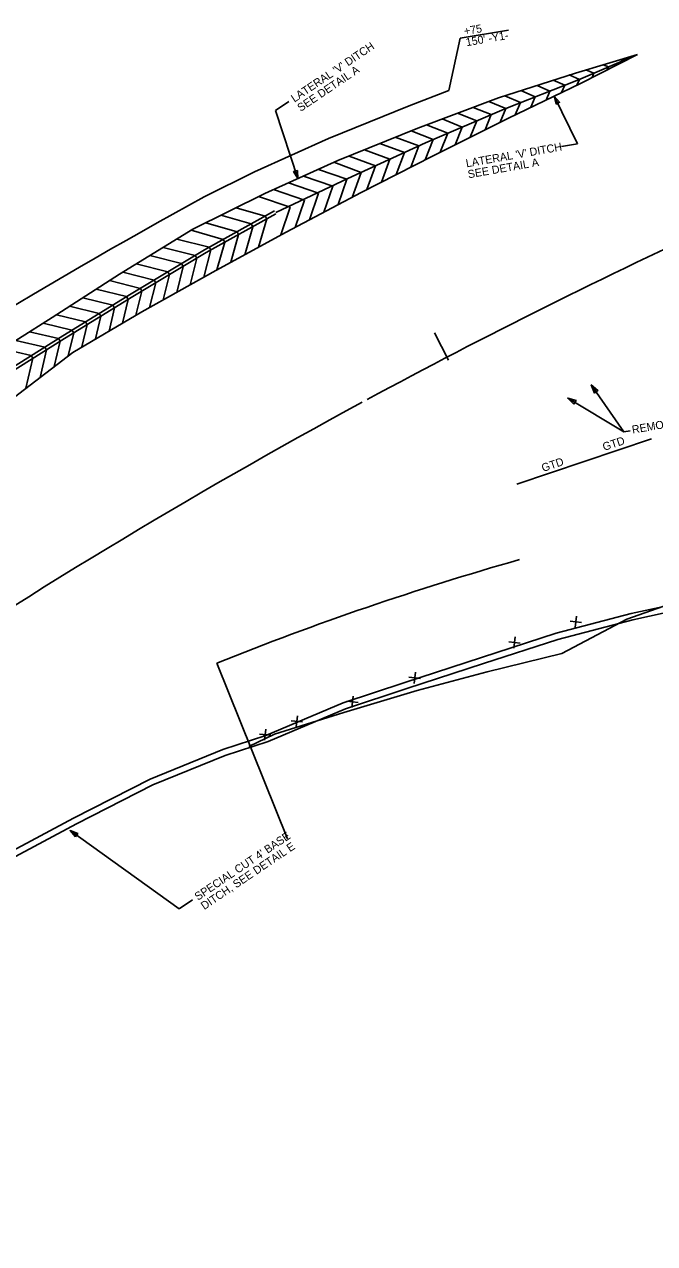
# Model space of a CAD drawing. Extents: x 2384780 to 2405432, y 547869 to 573706.
# Drawn here: x 2392798 to 2393192, y 553270 to 554032 of the extents above; entities that cross this region are included whole.
import ezdxf

# ---------------------------------------------------------------- set-up
doc = ezdxf.new("R2010")
doc.units = 0
for name, color, linetype in [('Old_Level_1', 7, 'Continuous'), ('Old_Level_18', 7, 'Continuous'), ('Old_Level_19', 7, 'Continuous'), ('Old_Level_23', 7, 'Continuous'), ('Old_Level_5', 7, 'Continuous'), ('Old_Level_63', 7, 'Continuous'), ('Prop Ditch Text', 7, 'Continuous'), ('Prop Grade To Drain Pattern Arrows', 7, 'Continuous'), ('Prop Rip Rap Class B Text', 7, 'Continuous'), ('Prop Special Cut Base Ditch Detail CELL', 7, 'Continuous')]:
    doc.layers.add(name, color=color, linetype=linetype)

# ---------------------------------------------------------------- blocks, each defined once
blk = doc.blocks.new('SPOT')
at = {"layer": 'Old_Level_1'}
for p, q in [((-5.48625, 4.61225), (5.48625, -4.61175)), ((-4.608, -5.326), (4.609, 5.325))]:
    blk.add_line(p, q, dxfattribs=at)
blk = doc.blocks.new('AH1')
at = {"layer": 'Old_Level_23'}
blk.add_lwpolyline([(-5.28, 1.32), (0, 0), (-5.28, -1.32)], close=True, dxfattribs=at)

msp = doc.modelspace()

# ---------------------------------------------------------------- linework, layer by layer
at = {"layer": 'Old_Level_1'}
for points in [[(2393152.24, 553806.97), (2393172.69, 553777.71)], [(2393137.51, 553798.8), (2393172.69, 553777.71), (2393176.55, 553778.37)]]:
    msp.add_lwpolyline(points, dxfattribs=at)
at = {"layer": 'Old_Level_18'}
for p, q in [((2393145.46, 553995.35), (2393181.12, 554013.48)), ((2393162.96, 554005.68), (2393159.66, 554006.99)), ((2393172.04, 554009.58), (2393170.39, 554010.24)), ((2393172.04, 554009.58), (2393171.68, 554008.68)), ((2393144.8, 553997.85), (2393138.39, 554000.64)), ((2393153.88, 554001.77), (2393148.93, 554003.74)), ((2393153.88, 554001.77), (2393152.8, 553999.09)), ((2393162.96, 554005.68), (2393162.24, 554003.89)), ((2393126.41, 553990.59), (2393118.4, 553994.07)), ((2393135.61, 553994.22), (2393128.49, 553997.31)), ((2393135.61, 553994.22), (2393133.61, 553989.63)), ((2393144.8, 553997.85), (2393143.25, 553994.28)), ((2393098.82, 553979.74), (2393088.1, 553984.03)), ((2393108.03, 553983.33), (2393098.2, 553987.6)), ((2393117.22, 553986.96), (2393108.3, 553990.84)), ((2393117.22, 553986.96), (2393114.44, 553980.55)), ((2393126.41, 553990.59), (2393123.98, 553984.97)), ((2393080.65, 553971.96), (2393068.69, 553976.76)), ((2393089.73, 553975.85), (2393078.4, 553980.39)), ((2393098.82, 553979.74), (2393095.35, 553971.08)), ((2393108.03, 553983.33), (2393104.7, 553975.66)), ((2393062.47, 553964.19), (2393049.27, 553969.48)), ((2393071.56, 553968.07), (2393058.98, 553973.12)), ((2393080.65, 553971.96), (2393076.55, 553961.74)), ((2393089.73, 553975.85), (2393085.95, 553966.41)), ((2393044.35, 553956.29), (2393029.7, 553961.7)), ((2393053.39, 553960.3), (2393039.73, 553965.77)), ((2393062.47, 553964.19), (2393057.75, 553952.4)), ((2393071.56, 553968.07), (2393067.15, 553957.07)), ((2393026.4, 553948.02), (2393010.49, 553953.89)), ((2393035.38, 553952.16), (2393020.1, 553957.79)), ((2393044.35, 553956.29), (2393039.49, 553943.11)), ((2393053.39, 553960.3), (2393048.31, 553947.64)), ((2393008.45, 553939.74), (2392991.28, 553946.08)), ((2393017.42, 553943.88), (2393000.89, 553949.98)), ((2393008.4, 553927.17), (2393052.89, 553949.99)), ((2393026.4, 553948.02), (2393021.11, 553933.69)), ((2393035.38, 553952.16), (2393030.3, 553938.4)), ((2392999.48, 553935.59), (2392981.65, 553941.63)), ((2393008.45, 553939.74), (2393002.7, 553924.17)), ((2393017.42, 553943.88), (2393011.92, 553928.98)), ((2392981.76, 553926.83), (2392962.95, 553933.2)), ((2392990.62, 553931.21), (2392972.3, 553937.41)), ((2392990.62, 553931.21), (2392985.09, 553914.89)), ((2392999.48, 553935.59), (2392994.07, 553919.62)), ((2392964.03, 553918.08), (2392944.25, 553924.77)), ((2392972.9, 553922.45), (2392953.6, 553928.99)), ((2392981.76, 553926.83), (2392976.11, 553910.16)), ((2392964.03, 553918.08), (2392958.15, 553900.7)), ((2392972.9, 553922.45), (2392967.13, 553905.43)), ((2393062.94, 553822.52), (2393054.12, 553839.44))]:
    msp.add_line(p, q, dxfattribs=at)
for points in [[(2392903.21, 553904.3), (2392948.07, 553926.49), (2392993.81, 553947.11), (2393043.8, 553967.43), (2393094.22, 553986.32), (2393142.33, 554001.75), (2393181.12, 554013.48)], [(2392955.08, 553914.79), (2393000.05, 553935.87), (2393048.59, 553958.25), (2393097.68, 553979.25), (2393144.33, 553997.67), (2393181.12, 554013.48)], [(2393052.89, 553949.99), (2393100.43, 553973.6), (2393145.46, 553995.35)], [(2393008.4, 553927.17), (2392961.43, 553902.43), (2392917.52, 553878.51), (2392871.18, 553852.58), (2392828.02, 553827.33), (2392788.08, 553796.64), (2392737.3, 553772.18), (2392695.19, 553745.21), (2392653.36, 553717.82), (2392609.9, 553687.76), (2392569.78, 553657.87), (2392527.37, 553625.8), (2392487.79, 553595.22), (2392448.41, 553564.38), (2392409.16, 553533.36)], [(2392399.88, 553545.9), (2392439.07, 553577.01), (2392478.7, 553607.5), (2392518.18, 553638.22), (2392560.98, 553670.48), (2392601.24, 553700.17), (2392644.37, 553731.39), (2392686.4, 553758.47), (2392731.91, 553780.31), (2392779.47, 553811.24), (2392821.9, 553837.73), (2392864.54, 553863.85), (2392910.39, 553891.36), (2392954.09, 553915.66)], [(2392930.16, 553917.63), (2392948.32, 553912.45), (2392948.32, 553912.45), (2392948.32, 553912.45), (2392949.29, 553910.7), (2392944.26, 553893.07)], [(2392401.07, 553544.3), (2392440.26, 553575.4), (2392479.89, 553605.89), (2392519.36, 553636.61), (2392562.12, 553668.84), (2392602.38, 553698.53), (2392645.47, 553729.72), (2392687.51, 553756.81), (2392733.01, 553778.65), (2392780.48, 553809.52), (2392822.91, 553836), (2392865.55, 553862.12), (2392911.36, 553889.61), (2392955.06, 553913.91)], [(2392911.28, 553908.29), (2392930.81, 553902.72), (2392930.81, 553902.72), (2392930.81, 553902.72), (2392931.78, 553900.96), (2392926.82, 553883.57)], [(2392920.72, 553912.96), (2392939.56, 553907.58), (2392939.56, 553907.58), (2392939.56, 553907.58), (2392940.54, 553905.83), (2392935.54, 553888.32)], [(2392391.62, 553557.07), (2392430.49, 553588.6), (2392470.2, 553618.99), (2392510.01, 553649.25), (2392553.45, 553681.27), (2392592.81, 553712.24), (2392635.85, 553744.24), (2392678.1, 553771.01), (2392724.33, 553791.76), (2392772.9, 553822.38), (2392815.18, 553849.12), (2392857.3, 553876.12), (2392903.21, 553904.3)], [(2392902.02, 553903.57), (2392922.05, 553897.85), (2392922.05, 553897.85), (2392922.05, 553897.85), (2392923.03, 553896.1), (2392918.1, 553878.82)], [(2392884.67, 553892.92), (2392904.66, 553887.93), (2392904.66, 553887.93), (2392904.66, 553887.93), (2392905.69, 553886.21), (2392901.53, 553869.56)], [(2392893.12, 553898.11), (2392913.25, 553893.08), (2392913.25, 553893.08), (2392913.25, 553893.08), (2392914.28, 553891.36), (2392910.02, 553874.31)], [(2392876.22, 553887.73), (2392896.07, 553882.77), (2392896.07, 553882.77), (2392896.07, 553882.77), (2392897.1, 553881.05), (2392893.04, 553864.81)], [(2392859.32, 553877.36), (2392878.9, 553872.46), (2392878.9, 553872.46), (2392878.9, 553872.46), (2392879.93, 553870.74), (2392876.07, 553855.32)], [(2392867.77, 553882.54), (2392887.48, 553877.62), (2392887.48, 553877.62), (2392887.48, 553877.62), (2392888.51, 553875.9), (2392884.56, 553860.06)], [(2392851.06, 553872.12), (2392870.31, 553867.31), (2392870.31, 553867.31), (2392870.31, 553867.31), (2392871.34, 553865.59), (2392867.56, 553850.46)], [(2392842.64, 553866.72), (2392861.74, 553862.13), (2392861.74, 553862.13), (2392861.74, 553862.13), (2392862.78, 553860.42), (2392859.22, 553845.58)], [(2392826.11, 553856.12), (2392844.65, 553851.67), (2392844.65, 553851.67), (2392844.65, 553851.67), (2392845.7, 553849.96), (2392842.27, 553835.67)], [(2392834.37, 553861.42), (2392853.19, 553856.9), (2392853.19, 553856.9), (2392853.19, 553856.9), (2392854.24, 553855.19), (2392850.74, 553840.63)], [(2392817.84, 553850.83), (2392836.11, 553846.44), (2392836.11, 553846.44), (2392836.11, 553846.44), (2392837.16, 553844.73), (2392833.79, 553830.71)], [(2392800.97, 553840.13), (2392819.05, 553835.95), (2392819.05, 553835.95), (2392819.05, 553835.95), (2392820.11, 553834.25), (2392816.45, 553818.45)], [(2392809.52, 553845.54), (2392827.57, 553841.2), (2392827.57, 553841.2), (2392827.57, 553841.2), (2392828.62, 553839.49), (2392825.17, 553825.15)], [(2392792.55, 553834.81), (2392810.55, 553830.65), (2392810.55, 553830.65), (2392810.55, 553830.65), (2392811.61, 553828.94), (2392807.61, 553811.65)], [(2392784.14, 553829.49), (2392802.06, 553825.34), (2392802.06, 553825.34), (2392802.06, 553825.34), (2392803.12, 553823.64), (2392798.77, 553804.86)]]:
    msp.add_lwpolyline(points, dxfattribs=at)
at = {"layer": 'Old_Level_19'}
for start, end in [(110.82846, 118.37122), (118.42377, 123.9393)]:
    msp.add_arc((2394828.31, 550434.92), 3822, start, end, dxfattribs=at)
at = {"layer": 'Old_Level_5'}
for p, q in [((2392963.17, 553983.99), (2392954.88, 553978.4)), ((2393129.06, 553987.43), (2393143.57, 553957.68)), ((2392968.85, 553935.86), (2392954.88, 553978.4)), ((2393143.57, 553957.68), (2393133.72, 553955.94))]:
    msp.add_line(p, q, dxfattribs=at)
for points in [[(2393130.26, 553982.42), (2393129.06, 553987.43), (2393132.48, 553983.57)], [(2392968.5, 553941), (2392968.85, 553935.86), (2392966.12, 553940.23)]]:
    msp.add_lwpolyline(points, close=True, dxfattribs=at)
at = {"layer": 'Old_Level_63'}
for p, q in [((2392962.24, 553523.29), (2392918.14, 553633.17)), ((2392938.11, 553581.03), (2392954.26, 553588.81))]:
    msp.add_line(p, q, dxfattribs=at)
for points in [[(2393063.09, 553990.88), (2393070.35, 554023.53), (2393100.43, 554028.71)], [(2392910.13, 553924.46), (2392941.66, 553940.06), (2392987.91, 553960.9), (2393038.34, 553981.4), (2393063.09, 553990.88)], [(2392954.26, 553588.81), (2392997.53, 553602.24), (2393043.36, 553616.05), (2393087.14, 553627.71), (2393133.91, 553639.1), (2393174.55, 553660.56), (2393261.49, 553691.17)]]:
    msp.add_lwpolyline(points, dxfattribs=at)
msp.add_arc((2394828.31, 550434.92), 3982, 118.79727, 123.9393, dxfattribs=at)
at = {"layer": 'Prop Ditch Text'}
for p in [(2392826.42, 553528.53), (2392902.9, 553485.25)]:
    msp.add_line(p, (2392894.61, 553479.66), dxfattribs=at)
msp.add_lwpolyline([(2392829.73, 553524.58), (2392826.42, 553528.53), (2392831.2, 553526.6)], close=True, dxfattribs=at)
for centre, radius, start, end in [((2393629.5, 551860.71), 1909.89, 105.86765, 108.86761), ((2393629.55, 551860.55), 1910.05, 108.86762, 111.86732)]:
    msp.add_arc(centre, radius, start, end, dxfattribs=at)
at = {"layer": 'Prop Grade To Drain Pattern Arrows'}
msp.add_line((2393105.76, 553744.93), (2393189.86, 553773.25), dxfattribs=at)
at = {"layer": 'Prop Special Cut Base Ditch Detail CELL'}
for points in [[(2393431.32, 553709.49), (2393357.37, 553699.67), (2393302.75, 553690.31), (2393257.86, 553681.9), (2393220.94, 553673.62), (2393177.22, 553664.1), (2393130.25, 553651.77), (2393083.63, 553636.74), (2393035.75, 553621.04), (2392997.2, 553608.43), (2392948.74, 553587.92), (2392921.95, 553579.12), (2392876.37, 553560.72), (2392828.54, 553536.35), (2392787.32, 553514.22), (2392744.89, 553491.62), (2392704.03, 553467.27), (2392661.48, 553438.97), (2392622.97, 553410.36), (2392582.55, 553381.89), (2392542.07, 553355), (2392501.34, 553327.48), (2392460.22, 553300.68), (2392415.27, 553273.9)], [(2393431.84, 553705.52), (2393357.97, 553695.72), (2393303.46, 553686.37), (2393258.66, 553677.98), (2393221.8, 553669.71), (2393178.16, 553660.21), (2393131.38, 553647.93), (2393084.86, 553632.94), (2393037, 553617.24), (2392998.6, 553604.68), (2392950.14, 553584.17), (2392923.33, 553575.36), (2392878.03, 553557.08), (2392830.39, 553532.81), (2392789.2, 553510.7), (2392746.85, 553488.14), (2392706.16, 553463.89), (2392663.78, 553435.7), (2392625.32, 553407.12), (2392584.81, 553378.59), (2392544.29, 553351.67), (2392503.55, 553324.14), (2392462.34, 553297.29), (2392417.31, 553270.46)]]:
    msp.add_lwpolyline(points, dxfattribs=at)

# ---------------------------------------------------------------- block references
at = {"layer": 'Old_Level_23'}
for p, xscale, yscale, rotation in [((2393152.24, 553806.97), 0.9999997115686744, 0.9999997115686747, 124.95169310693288), ((2393137.51, 553798.8), 0.999999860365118, 0.9999998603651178, 149.0570627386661)]:
    msp.add_blockref('AH1', p, dxfattribs=dict(at, xscale=xscale, yscale=yscale, rotation=rotation))
at = {"layer": 'Old_Level_63', "xscale": 0.5000000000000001, "yscale": 0.5, "rotation": 33.999927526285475}
for p in [(2393142.61, 553658.93), (2393104.16, 553646.08), (2393041.83, 553623.98), (2393002.88, 553608.91), (2392968.1, 553596.75), (2392948.42, 553588.42)]:
    msp.add_blockref('SPOT', p, dxfattribs=at)

# ---------------------------------------------------------------- texts
at = {"layer": 'Old_Level_1'}
for s, rotation, p in [('REMOVE', 9.78334, (2393178.12, 553776.51)), ('GTD', 18.60879, (2393122.14, 553752.56))]:
    msp.add_text(s, height=5, rotation=rotation, dxfattribs=at).set_placement(p)
at = {"layer": 'Old_Level_5'}
for s, rotation, p in [("LATERAL 'V' DITCH", 33.99993, (2392966.64, 553983.32)), ('SEE DETAIL A', 33.99993, (2392970.56, 553977.51)), ("LATERAL 'V' DITCH", 10.00007, (2393074.28, 553942.92)), ('SEE DETAIL A', 10.00007, (2393075.5, 553936.03))]:
    msp.add_text(s, height=5, rotation=rotation, dxfattribs=at).set_placement(p)
at = {"layer": 'Old_Level_63'}
for s, p in [('+75', (2393073.06, 554025.47)), ("150' -Y1-", (2393074.25, 554018.57))]:
    msp.add_text(s, height=5, rotation=9.78343, dxfattribs=at).set_placement(p)
at = {"layer": 'Prop Ditch Text'}
for s, p in [("SPECIAL CUT 4' BASE", (2392906.33, 553484.62)), ('DITCH, SEE DETAIL E', (2392910.25, 553478.82))]:
    msp.add_text(s, height=5, rotation=34, dxfattribs=at).set_placement(p)
at = {"layer": 'Prop Rip Rap Class B Text'}
msp.add_text('GTD', height=5, rotation=18.35435, dxfattribs=at).set_placement((2393160.29, 553765.71))

doc.saveas('drawing.dxf')
